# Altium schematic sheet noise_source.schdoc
size 400 x 277 mm; Device: default420x297; Symbol: default420x297; Name: default420x297; Size: "User"; Id: /; File: noise_source; Sheet: /
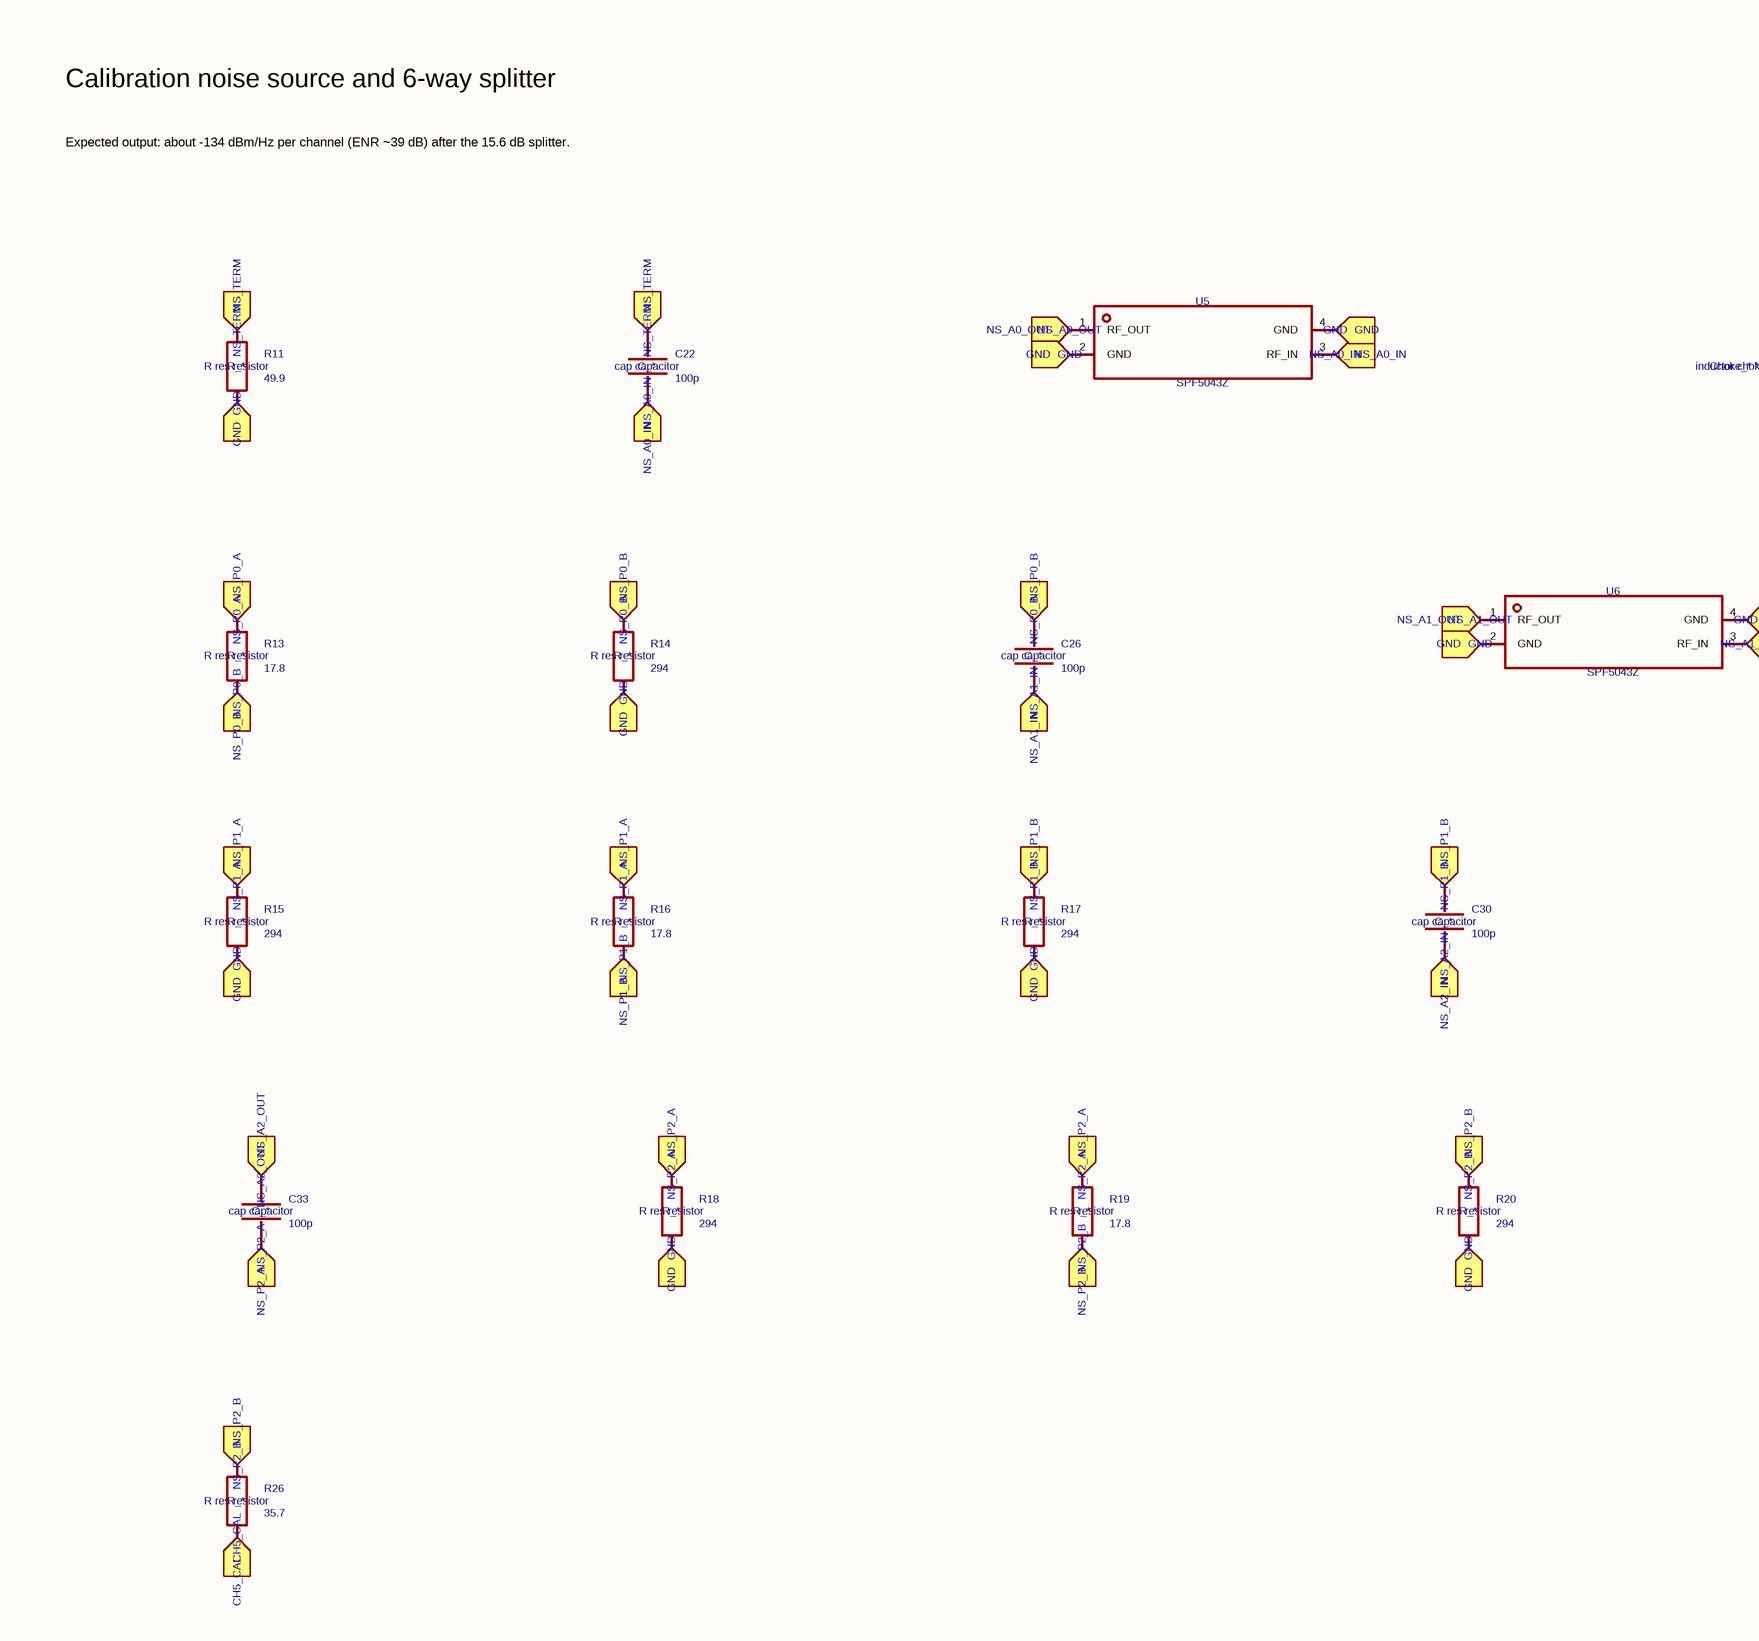
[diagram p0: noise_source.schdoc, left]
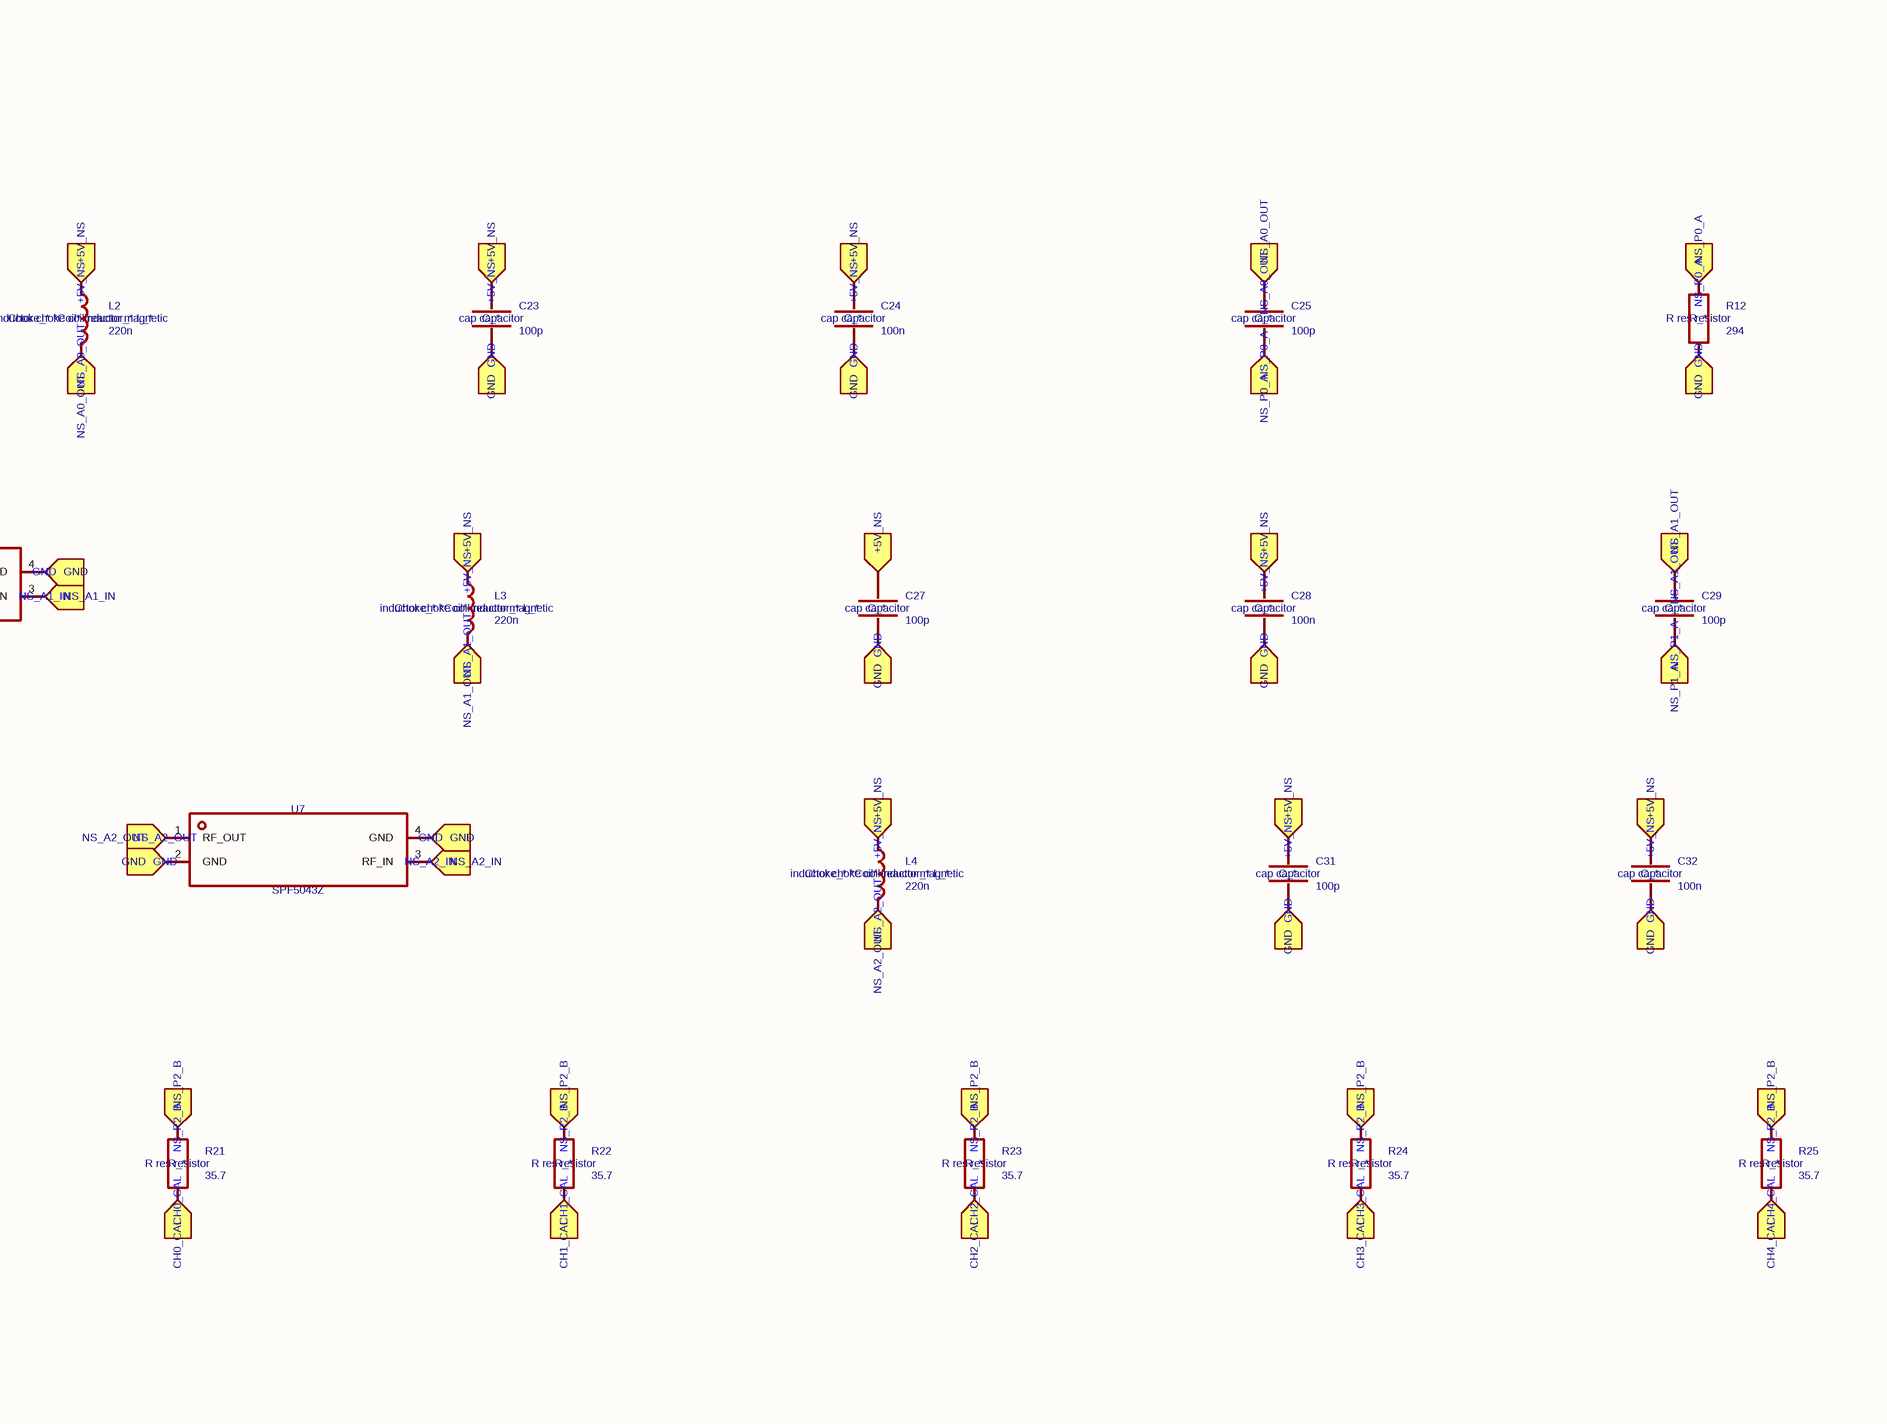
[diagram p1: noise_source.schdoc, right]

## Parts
C22  value 100p  ki_keywords: cap capacitor  ki_fp_filters: C_*  [Capacitor_SMD:C_0402_1005Metric]  (hidden comment: Device_C)
C23  value 100p  ki_keywords: cap capacitor  ki_fp_filters: C_*  [Capacitor_SMD:C_0402_1005Metric]  (hidden comment: Device_C)
C24  value 100n  ki_keywords: cap capacitor  ki_fp_filters: C_*  [Capacitor_SMD:C_0402_1005Metric]  (hidden comment: Device_C)
C25  value 100p  ki_keywords: cap capacitor  ki_fp_filters: C_*  [Capacitor_SMD:C_0402_1005Metric]  (hidden comment: Device_C)
C26  value 100p  ki_keywords: cap capacitor  ki_fp_filters: C_*  [Capacitor_SMD:C_0402_1005Metric]  (hidden comment: Device_C)
C27  value 100p  ki_keywords: cap capacitor  ki_fp_filters: C_*  [Capacitor_SMD:C_0402_1005Metric]  (hidden comment: Device_C)
C28  value 100n  ki_keywords: cap capacitor  ki_fp_filters: C_*  [Capacitor_SMD:C_0402_1005Metric]  (hidden comment: Device_C)
C29  value 100p  ki_keywords: cap capacitor  ki_fp_filters: C_*  [Capacitor_SMD:C_0402_1005Metric]  (hidden comment: Device_C)
C30  value 100p  ki_keywords: cap capacitor  ki_fp_filters: C_*  [Capacitor_SMD:C_0402_1005Metric]  (hidden comment: Device_C)
C31  value 100p  ki_keywords: cap capacitor  ki_fp_filters: C_*  [Capacitor_SMD:C_0402_1005Metric]  (hidden comment: Device_C)
C32  value 100n  ki_keywords: cap capacitor  ki_fp_filters: C_*  [Capacitor_SMD:C_0402_1005Metric]  (hidden comment: Device_C)
C33  value 100p  ki_keywords: cap capacitor  ki_fp_filters: C_*  [Capacitor_SMD:C_0402_1005Metric]  (hidden comment: Device_C)
L2  value 220n  ki_keywords: inductor choke coil reactor magnetic  ki_fp_filters: Choke_* *Coil* Inductor_* L_*  [Inductor_SMD:L_0603_1608Metric]  (hidden comment: Device_L)
L3  value 220n  ki_keywords: inductor choke coil reactor magnetic  ki_fp_filters: Choke_* *Coil* Inductor_* L_*  [Inductor_SMD:L_0603_1608Metric]  (hidden comment: Device_L)
L4  value 220n  ki_keywords: inductor choke coil reactor magnetic  ki_fp_filters: Choke_* *Coil* Inductor_* L_*  [Inductor_SMD:L_0603_1608Metric]  (hidden comment: Device_L)
R11  value 49.9  ki_keywords: R res resistor  ki_fp_filters: R_*  [Resistor_SMD:R_0402_1005Metric]  (hidden comment: Device_R)
R12  value 294  ki_keywords: R res resistor  ki_fp_filters: R_*  [Resistor_SMD:R_0402_1005Metric]  (hidden comment: Device_R)
R13  value 17.8  ki_keywords: R res resistor  ki_fp_filters: R_*  [Resistor_SMD:R_0402_1005Metric]  (hidden comment: Device_R)
R14  value 294  ki_keywords: R res resistor  ki_fp_filters: R_*  [Resistor_SMD:R_0402_1005Metric]  (hidden comment: Device_R)
R15  value 294  ki_keywords: R res resistor  ki_fp_filters: R_*  [Resistor_SMD:R_0402_1005Metric]  (hidden comment: Device_R)
R16  value 17.8  ki_keywords: R res resistor  ki_fp_filters: R_*  [Resistor_SMD:R_0402_1005Metric]  (hidden comment: Device_R)
R17  value 294  ki_keywords: R res resistor  ki_fp_filters: R_*  [Resistor_SMD:R_0402_1005Metric]  (hidden comment: Device_R)
R18  value 294  ki_keywords: R res resistor  ki_fp_filters: R_*  [Resistor_SMD:R_0402_1005Metric]  (hidden comment: Device_R)
R19  value 17.8  ki_keywords: R res resistor  ki_fp_filters: R_*  [Resistor_SMD:R_0402_1005Metric]  (hidden comment: Device_R)
R20  value 294  ki_keywords: R res resistor  ki_fp_filters: R_*  [Resistor_SMD:R_0402_1005Metric]  (hidden comment: Device_R)
R21  value 35.7  ki_keywords: R res resistor  ki_fp_filters: R_*  [Resistor_SMD:R_0402_1005Metric]  (hidden comment: Device_R)
R22  value 35.7  ki_keywords: R res resistor  ki_fp_filters: R_*  [Resistor_SMD:R_0402_1005Metric]  (hidden comment: Device_R)
R23  value 35.7  ki_keywords: R res resistor  ki_fp_filters: R_*  [Resistor_SMD:R_0402_1005Metric]  (hidden comment: Device_R)
R24  value 35.7  ki_keywords: R res resistor  ki_fp_filters: R_*  [Resistor_SMD:R_0402_1005Metric]  (hidden comment: Device_R)
R25  value 35.7  ki_keywords: R res resistor  ki_fp_filters: R_*  [Resistor_SMD:R_0402_1005Metric]  (hidden comment: Device_R)
R26  value 35.7  ki_keywords: R res resistor  ki_fp_filters: R_*  [Resistor_SMD:R_0402_1005Metric]  (hidden comment: Device_R)
U5  value SPF5043Z  [prc:SOT343_L2.0-W1.3-P1.30-LS2.1-BL]  (hidden comment: prc_SPF5043Z)
U6  value SPF5043Z  [prc:SOT343_L2.0-W1.3-P1.30-LS2.1-BL]  (hidden comment: prc_SPF5043Z)
U7  value SPF5043Z  [prc:SOT343_L2.0-W1.3-P1.30-LS2.1-BL]  (hidden comment: prc_SPF5043Z)

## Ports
+5V_NS (in), CH0_CAL (in), CH1_CAL (in), CH2_CAL (in), CH3_CAL (in), CH4_CAL (in), CH5_CAL (in), GND (in), NS_A0_IN (in), NS_A0_OUT (in), NS_A1_IN (in), NS_A1_OUT (in), NS_A2_IN (in), NS_A2_OUT (in), NS_P0_A (in), NS_P0_B (in), NS_P1_A (in), NS_P1_B (in), NS_P2_A (in), NS_P2_B (in), NS_TERM (in)

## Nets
+5V_NS: C23.1 C24.1 C27.1 C28.1 C31.1 C32.1 L2.1 L3.1 L4.1 ; port +5V_NS
CH0_CAL: R21.2 ; port CH0_CAL
CH1_CAL: R22.2 ; port CH1_CAL
CH2_CAL: R23.2 ; port CH2_CAL
CH3_CAL: R24.2 ; port CH3_CAL
CH4_CAL: R25.2 ; port CH4_CAL
CH5_CAL: R26.2 ; port CH5_CAL
GND: C23.2 C24.2 C27.2 C28.2 C31.2 C32.2 R11.2 R12.2 R14.2 R15.2 R17.2 R18.2 R20.2 U5.2(GND) U5.4(GND) U6.2(GND) U6.4(GND) U7.2(GND) U7.4(GND) ; port GND
NS_A0_IN: C22.2 U5.3(RF_IN) ; port NS_A0_IN
NS_A0_OUT: C25.1 L2.2 U5.1(RF_OUT) ; port NS_A0_OUT
NS_A1_IN: C26.2 U6.3(RF_IN) ; port NS_A1_IN
NS_A1_OUT: C29.1 L3.2 U6.1(RF_OUT) ; port NS_A1_OUT
NS_A2_IN: C30.2 U7.3(RF_IN) ; port NS_A2_IN
NS_A2_OUT: C33.1 L4.2 U7.1(RF_OUT) ; port NS_A2_OUT
NS_P0_A: C25.2 R12.1 R13.1 ; port NS_P0_A
NS_P0_B: C26.1 R13.2 R14.1 ; port NS_P0_B
NS_P1_A: C29.2 R15.1 R16.1 ; port NS_P1_A
NS_P1_B: C30.1 R16.2 R17.1 ; port NS_P1_B
NS_P2_A: C33.2 R18.1 R19.1 ; port NS_P2_A
NS_P2_B: R19.2 R20.1 R21.1 R22.1 R23.1 R24.1 R25.1 R26.1 ; port NS_P2_B
NS_TERM: C22.1 R11.1 ; port NS_TERM

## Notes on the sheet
- Calibration noise source and 6-way splitter
- Expected output: about -134 dBm/Hz per channel (ENR ~39 dB) after the 15.6 dB splitter.

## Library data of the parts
C22 = Device_C: UniqueId: 7f35450ac3171d20; KiLib_Generator: SMD_2terminal_chip_molded; AddInBom: yes
C23 = Device_C: UniqueId: 8bc5c1e1749a19fa; KiLib_Generator: SMD_2terminal_chip_molded; AddInBom: yes
C24 = Device_C: UniqueId: 7c674fedd66d7165; KiLib_Generator: SMD_2terminal_chip_molded; AddInBom: yes
C25 = Device_C: UniqueId: d99985aa138ce050; KiLib_Generator: SMD_2terminal_chip_molded; AddInBom: yes
C26 = Device_C: UniqueId: 5bc8fc857418e778; KiLib_Generator: SMD_2terminal_chip_molded; AddInBom: yes
C27 = Device_C: UniqueId: a26eb100929f0697; KiLib_Generator: SMD_2terminal_chip_molded; AddInBom: yes
C28 = Device_C: UniqueId: e3aeb17489c0ab5d; KiLib_Generator: SMD_2terminal_chip_molded; AddInBom: yes
C29 = Device_C: UniqueId: 5bfcee5f0e3d202c; KiLib_Generator: SMD_2terminal_chip_molded; AddInBom: yes
C30 = Device_C: UniqueId: a2ee6ceb65d30336; KiLib_Generator: SMD_2terminal_chip_molded; AddInBom: yes
C31 = Device_C: UniqueId: cc1d00c51cc12124; KiLib_Generator: SMD_2terminal_chip_molded; AddInBom: yes
C32 = Device_C: UniqueId: d2625f4b4bd439ef; KiLib_Generator: SMD_2terminal_chip_molded; AddInBom: yes
C33 = Device_C: UniqueId: deb55bbe20a101cf; KiLib_Generator: SMD_2terminal_chip_molded; AddInBom: yes
L2 = Device_L: UniqueId: 3f6ee2b1a34b017f; KiLib_Generator: SMD_2terminal_chip_molded; AddInBom: yes
L3 = Device_L: UniqueId: 510f7e7047da8839; KiLib_Generator: SMD_2terminal_chip_molded; AddInBom: yes
L4 = Device_L: UniqueId: fd5a5c0f77d1aabb; KiLib_Generator: SMD_2terminal_chip_molded; AddInBom: yes
R11 = Device_R: UniqueId: 763cf8d5648cb4fd; KiLib_Generator: SMD_2terminal_chip_molded; AddInBom: yes
R12 = Device_R: UniqueId: 15ac9218146e0f4b; KiLib_Generator: SMD_2terminal_chip_molded; AddInBom: yes
R13 = Device_R: UniqueId: ff4077a9ca69db92; KiLib_Generator: SMD_2terminal_chip_molded; AddInBom: yes
R14 = Device_R: UniqueId: 8b54177fc4d64d35; KiLib_Generator: SMD_2terminal_chip_molded; AddInBom: yes
R15 = Device_R: UniqueId: feece054417b9159; KiLib_Generator: SMD_2terminal_chip_molded; AddInBom: yes
R16 = Device_R: UniqueId: 3c543c7c58e1cc80; KiLib_Generator: SMD_2terminal_chip_molded; AddInBom: yes
R17 = Device_R: UniqueId: 6346d187b4e0bc9c; KiLib_Generator: SMD_2terminal_chip_molded; AddInBom: yes
R18 = Device_R: UniqueId: 5f673669f0d56d8f; KiLib_Generator: SMD_2terminal_chip_molded; AddInBom: yes
R19 = Device_R: UniqueId: a32210a39874d8f8; KiLib_Generator: SMD_2terminal_chip_molded; AddInBom: yes
R20 = Device_R: UniqueId: 13e77c54ede4b306; KiLib_Generator: SMD_2terminal_chip_molded; AddInBom: yes
R21 = Device_R: UniqueId: c77b08197b178948; KiLib_Generator: SMD_2terminal_chip_molded; AddInBom: yes
R22 = Device_R: UniqueId: fa394caafc8878d8; KiLib_Generator: SMD_2terminal_chip_molded; AddInBom: yes
R23 = Device_R: UniqueId: d92c635076b33213; KiLib_Generator: SMD_2terminal_chip_molded; AddInBom: yes
R24 = Device_R: UniqueId: f7952e9f9cd6773b; KiLib_Generator: SMD_2terminal_chip_molded; AddInBom: yes
R25 = Device_R: UniqueId: 6f4c4beafd605d3e; KiLib_Generator: SMD_2terminal_chip_molded; AddInBom: yes
R26 = Device_R: UniqueId: 09b823a69019dbbf; KiLib_Generator: SMD_2terminal_chip_molded; AddInBom: yes
U5 = prc_SPF5043Z: Manufacturer: Qorvo; ki_keywords: RF Amplifiers; UniqueId: adf583383e4d69d4; AddInBom: yes
U6 = prc_SPF5043Z: Manufacturer: Qorvo; ki_keywords: RF Amplifiers; UniqueId: 124c013cfc851acc; AddInBom: yes
U7 = prc_SPF5043Z: Manufacturer: Qorvo; ki_keywords: RF Amplifiers; UniqueId: 4ec783ed4741de1f; AddInBom: yes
